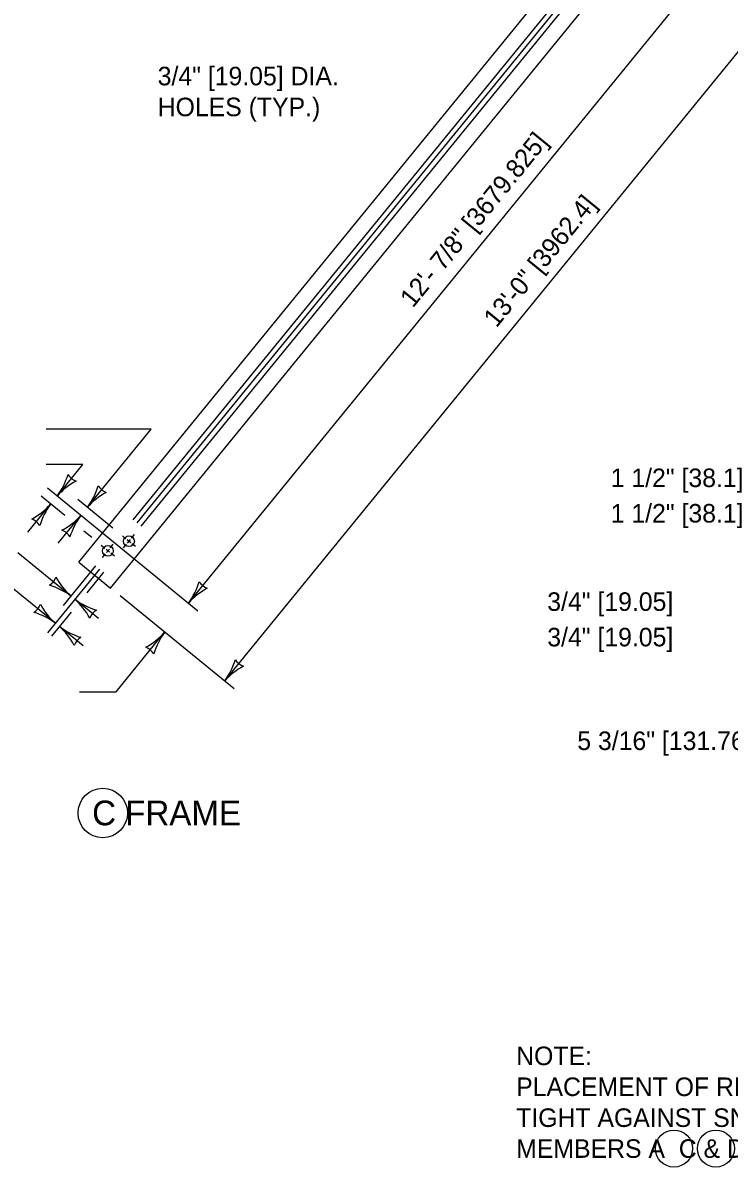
# Model space of a CAD drawing. Extents: x 49991.4 to 50021, y 49987.6 to 50011.4.
# Drawn here: x 50007.266 to 50009.55, y 49993.415 to 49997.118 of the extents above; entities that cross this region are included whole.
import ezdxf

# ---------------------------------------------------------------- set-up
doc = ezdxf.new("R2010")
doc.units = 0
for name, color, linetype in [('Level 1', 7, 'Continuous'), ('Level 2', 7, 'Continuous'), ('Level 3', 7, 'Continuous'), ('Level 5', 7, 'Continuous')]:
    doc.layers.add(name, color=color, linetype=linetype)

msp = doc.modelspace()

# ---------------------------------------------------------------- linework, layer by layer
at = {"layer": 'Level 1'}
for p, q in [((50007.4465, 49995.3728), (50009.6889, 49998.1205)), ((50007.5494, 49995.2888), (50009.7272, 49997.9577)), ((50007.6228, 49995.51), (50009.5947, 49997.926)), ((50007.6356, 49995.4996), (50009.6075, 49997.9156)), ((50007.6486, 49995.489), (50009.6203, 49997.9052)), ((50007.4465, 49995.3728), (50007.5494, 49995.2888)), ((50007.4467, 49995.3729), (50007.4467, 49995.3729))]:
    msp.add_line(p, q, dxfattribs=at)
at = {"layer": 'Level 2'}
for centre, radius in [((50007.5243, 49994.561), 0.08), ((50009.3721, 49993.4753), 0.06), ((50009.5076, 49993.4753), 0.06)]:
    msp.add_circle(centre, radius, dxfattribs=at)
at = {"layer": 'Level 3'}
for p, q in [((50007.8012, 49995.24), (50009.8935, 49997.8039)), ((50007.918, 49994.9878), (50010.1605, 49997.7357)), ((50007.681, 49995.8036), (50007.3411, 49995.8036)), ((50007.4744, 49995.5502), (50007.681, 49995.8036)), ((50007.4598, 49995.6888), (50007.3411, 49995.6888)), ((50007.3766, 49995.5867), (50007.4598, 49995.6888)), ((50007.8322, 49995.2147), (50007.3457, 49995.612)), ((50007.4011, 49995.5235), (50007.3245, 49995.5861)), ((50007.5566, 49995.4832), (50007.4434, 49995.5755)), ((50007.2817, 49995.4703), (50007.3555, 49995.5608)), ((50007.3795, 49995.4338), (50007.4532, 49995.5242)), ((50007.4883, 49995.4521), (50007.4631, 49995.4728)), ((50007.4211, 49995.2631), (50007.2498, 49995.403)), ((50007.5139, 49995.3505), (50007.3455, 49995.1443)), ((50007.5011, 49995.361), (50007.3958, 49995.2322)), ((50007.5268, 49995.34), (50007.4722, 49995.273)), ((50007.3708, 49995.1752), (50007.2324, 49995.2882)), ((50007.5106, 49995.19), (50007.434, 49995.2526)), ((50007.949, 49994.9625), (50007.5804, 49995.2635)), ((50007.4217, 49995.211), (50007.3585, 49995.1337)), ((50007.4604, 49995.102), (50007.3838, 49995.1646)), ((50007.5673, 49994.9528), (50007.7244, 49995.1459)), ((50007.4487, 49994.9528), (50007.5673, 49994.9528))]:
    msp.add_line(p, q, dxfattribs=at)
for centre, radius, start, end in [((50007.189, 49995.7248), 0.233, 323.6512, 342.901), ((50007.4576, 49995.6861), 0.0548, 212.9627, 248.685), ((50007.543, 49995.4393), 0.2223, 118.2799, 138.4634), ((50007.2868, 49995.6884), 0.233, 323.6365, 342.8864), ((50007.5554, 49995.6496), 0.0548, 212.9481, 248.6704), ((50007.6408, 49995.4028), 0.2223, 118.2652, 138.4488), ((50007.1891, 49995.7082), 0.2223, 298.2668, 318.4503), ((50007.5431, 49995.4226), 0.233, 143.6381, 162.888), ((50007.2745, 49995.4614), 0.0548, 32.9496, 68.672), ((50007.2868, 49995.6717), 0.2223, 298.2668, 318.4503), ((50007.6408, 49995.3861), 0.233, 143.6381, 162.888), ((50007.3722, 49995.4248), 0.0548, 32.9496, 68.672), ((50007.3218, 49995.3442), 0.0548, 302.8992, 338.6215), ((50007.5687, 49995.4294), 0.2223, 208.2164, 228.3999), ((50007.2828, 49995.0756), 0.233, 53.5877, 72.8375), ((50007.6136, 49995.3782), 0.233, 323.6097, 342.8595), ((50007.9675, 49995.0925), 0.2223, 118.2384, 138.4219), ((50007.8823, 49995.3393), 0.0548, 212.9212, 248.6435), ((50007.2863, 49995.0864), 0.2223, 28.1992, 48.3827), ((50007.5723, 49995.4401), 0.233, 233.5705, 252.8204), ((50007.2714, 49995.2563), 0.0548, 302.9081, 338.6304), ((50007.2325, 49994.9877), 0.233, 53.5966, 72.8464), ((50007.5183, 49995.3415), 0.2223, 208.2253, 228.4088), ((50007.5332, 49995.1715), 0.0548, 122.882, 158.6044), ((50007.2361, 49994.9984), 0.2223, 28.1992, 48.3827), ((50007.5221, 49995.3521), 0.233, 233.5705, 252.8204), ((50007.4831, 49995.0835), 0.0548, 122.882, 158.6044), ((50007.558, 49995.2933), 0.2223, 298.2824, 318.4659), ((50007.9121, 49995.0078), 0.233, 143.6537, 162.9035), ((50007.6434, 49995.0465), 0.0548, 32.9652, 68.6875), ((50007.7304, 49995.126), 0.233, 323.6092, 342.859), ((50007.9991, 49995.0871), 0.0548, 212.9207, 248.643), ((50008.0843, 49994.8403), 0.2223, 118.2379, 138.4214)]:
    msp.add_arc(centre, radius, start, end, dxfattribs=at)
at = {"layer": 'Level 5'}
for p, q in [((50007.6169, 49995.4502), (50007.6264, 49995.4618)), ((50007.5309, 49995.4173), (50007.5193, 49995.4268)), ((50007.5486, 49995.4191), (50007.5581, 49995.4307)), ((50007.5992, 49995.4484), (50007.5876, 49995.4579)), ((50007.5915, 49995.4192), (50007.601, 49995.4308)), ((50007.6147, 49995.4357), (50007.6031, 49995.4452)), ((50007.6042, 49995.4347), (50007.6137, 49995.4463)), ((50007.6302, 49995.423), (50007.6186, 49995.4325)), ((50007.5232, 49995.3881), (50007.5327, 49995.3997)), ((50007.5464, 49995.4046), (50007.5348, 49995.4141)), ((50007.5359, 49995.4036), (50007.5454, 49995.4152)), ((50007.5619, 49995.3919), (50007.5503, 49995.4014))]:
    msp.add_line(p, q, dxfattribs=at)
for centre in [(50007.5406, 49995.4093), (50007.6089, 49995.4404)]:
    msp.add_circle(centre, 0.0175, dxfattribs=at)

# ---------------------------------------------------------------- texts
at = {"layer": 'Level 2'}
for s, height, p in [('3/4" [19.05] DIA.', 0.06, (50007.7018, 49996.9157)), ('HOLES (TYP.)', 0.06, (50007.7018, 49996.8157)), ('1 1/2" [38.1]', 0.06, (50009.1672, 49995.6157)), ('1 1/2" [38.1]', 0.06, (50009.1672, 49995.5009)), (' 3/4" [19.05]', 0.06, (50008.9398, 49995.2151)), (' 3/4" [19.05]', 0.06, (50008.9398, 49995.1003)), ('5 3/16" [131.763]', 0.06, (50009.0593, 49994.7649)), ('C FRAME', 0.08, (50007.4899, 49994.5213)), ('NOTE:', 0.06, (50008.8615, 49993.7453)), ('PLACEMENT OF REBAR ANCHORS', 0.06, (50008.8615, 49993.6453)), ('TIGHT AGAINST SNOW FENCE', 0.06, (50008.8615, 49993.5453)), ('MEMBERS A  C & D IS CRITICAL', 0.06, (50008.8615, 49993.4453))]:
    msp.add_text(s, height=height, dxfattribs=at).set_placement(p)
for s, p in [('12\'- 7/8" [3679.825]', (50008.5274, 49996.1932)), ('13\'-0" [3962.4]', (50008.7976, 49996.1288))]:
    msp.add_text(s, height=0.06, rotation=50.7823, dxfattribs=at).set_placement(p)

doc.saveas('drawing.dxf')
